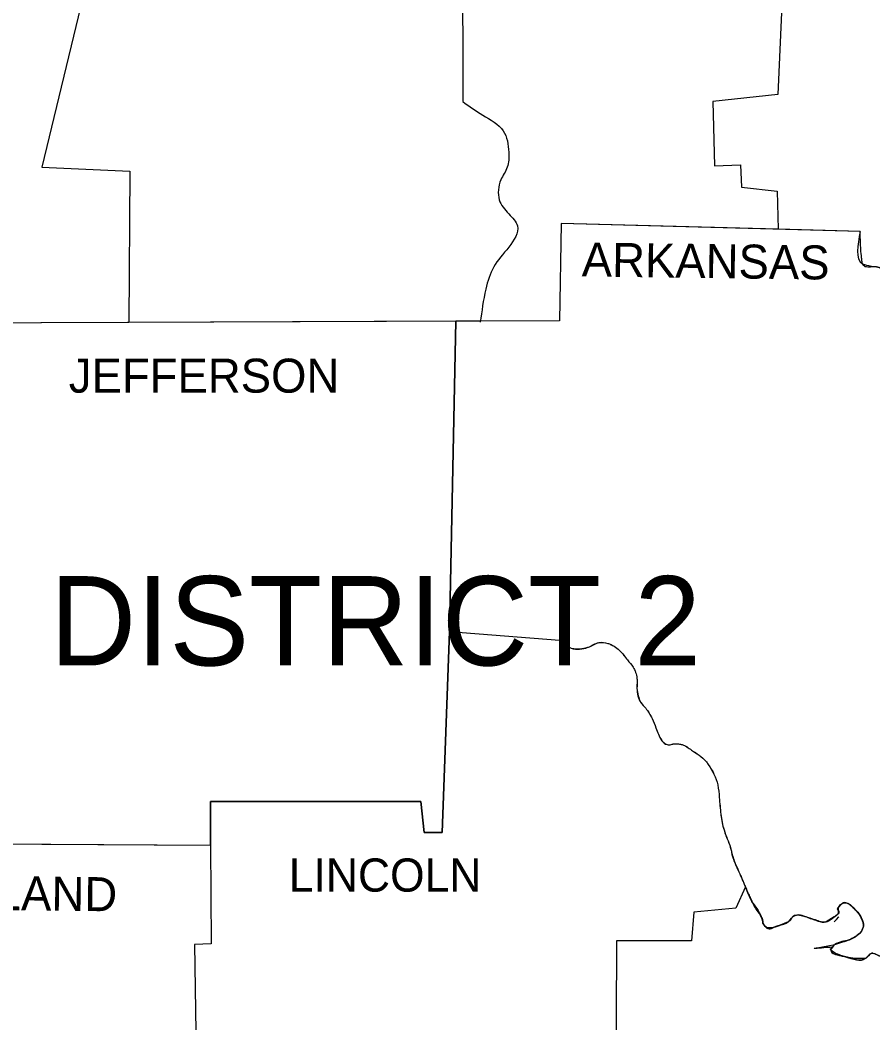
# Model space of a CAD drawing. Extents: x 3046 to 131673, y -8885 to 10756.
# Drawn here: x 28781 to 29835, y 6426 to 7667 of the extents above; entities that cross this region are included whole.
import ezdxf

# ---------------------------------------------------------------- set-up
doc = ezdxf.new("R2010")
doc.units = 0
for name, color, linetype in [('1', 7, 'Continuous'), ('2', 7, 'Continuous'), ('3', 7, 'Continuous'), ('R_Annotation', 7, 'Continuous')]:
    doc.layers.add(name, color=color, linetype=linetype)

msp = doc.modelspace()

# ---------------------------------------------------------------- linework, layer by layer
at = {"layer": '1'}
for points in [[(29187.61348452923, 8119.400186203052), (29189.570298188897, 7944.265365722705), (29327.52565951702, 7941.330145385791), (29328.50406627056, 7565.621927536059)], [(28801.142791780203, 8074.393472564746), (28857.890387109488, 8070.47984524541), (28858.868794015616, 7696.7284411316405), (28807.9916394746, 7484.414161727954), (28916.59479625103, 7479.52212750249), (28915.578457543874, 7292.515822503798)], [(29729.650861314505, 7842.511056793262), (29717.909979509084, 7574.427588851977), (29637.68062056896, 7565.621927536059), (29639.63743419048, 7486.370975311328), (29671.924859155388, 7487.349382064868), (29672.903266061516, 7459.953991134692), (29716.931572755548, 7455.06195713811), (29718.362445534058, 7407.843152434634)], [(29819.664288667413, 7405.163209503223), (29449.8265115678, 7414.947277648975), (29447.86969794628, 7294.603239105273), (28699.388482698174, 7291.668018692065)], [(29319.809376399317, 7294.101041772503), (29311.871150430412, 6910.089359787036), (29447.86969794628, 6899.326884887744)], [(29311.871150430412, 6910.089359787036), (29303.065488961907, 6661.574028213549), (29280.562132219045, 6661.574028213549), (29276.648504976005, 6699.731894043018), (29016.39229155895, 6699.731894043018), (29016.39229155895, 6644.941112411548)], [(28668.079464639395, 6647.876332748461), (29016.39229155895, 6645.919519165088)], [(29016.39229155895, 6645.919519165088), (29017.370698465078, 6523.618667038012), (28996.824155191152, 6522.640260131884), (29002.694596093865, 6116.601431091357)], [(29677.79530001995, 6594.063957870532), (29666.05441821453, 6567.646973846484), (29614.198856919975, 6562.754939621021), (29611.263636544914, 6527.532294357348), (29518.314988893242, 6527.532294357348), (29517.336581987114, 6234.988655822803)], [(29787.37686354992, 6551.014057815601), (29790.312084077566, 6553.949278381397), (29793.247304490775, 6556.88449871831), (29793.247304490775, 6556.88449871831)]]:
    msp.add_lwpolyline(points, dxfattribs=at)
for points in [[(29328.50406627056, 7565.621927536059), (29352.964236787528, 7548.98901158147), (29378.40281390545, 7529.420875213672), (29385.251661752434, 7503.003891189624), (29383.294848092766, 7484.414161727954), (29375.467593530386, 7468.759652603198), (29373.510779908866, 7444.299482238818), (29385.251661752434, 7426.688159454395), (29396.014136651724, 7412.0120571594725), (29385.251661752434, 7385.595073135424), (29366.66193210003, 7361.134902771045), (29356.877864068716, 7333.7395118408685), (29350.02901625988, 7292.646425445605)], [(29819.664288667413, 7405.163209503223), (29822.599509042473, 7365.048530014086), (29846.08127265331, 7359.178089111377), (29855.865340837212, 7348.415613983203), (29860.75737487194, 7325.912257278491), (29877.390290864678, 7316.128189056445), (29899.893647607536, 7302.430493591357), (29913.591343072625, 7292.646425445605), (29923.375411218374, 7276.99191632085), (29929.24585215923, 7251.5533390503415), (29944.90036124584, 7234.92042324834), (29966.425311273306, 7227.093168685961), (29982.079820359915, 7208.5034392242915), (29991.86388835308, 7182.086455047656), (30007.518397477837, 7170.345573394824), (30023.172906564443, 7149.799030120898), (30031.000161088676, 7140.9933688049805), (30044.697856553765, 7117.51160519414), (30058.39555201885, 7105.77072338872), (30068.1796202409, 7098.921875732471), (30083.834129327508, 7094.0298415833), (30103.402265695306, 7081.31055302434), (30116.121554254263, 7061.742416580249), (30116.121554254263, 7047.0663142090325), (30111.229520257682, 7024.562957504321), (30107.315892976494, 7001.081193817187), (30105.359079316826, 6974.664209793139), (30103.402265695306, 6951.1824461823), (30112.207927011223, 6931.614309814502), (30107.315892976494, 6902.262105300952), (30097.531824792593, 6886.607596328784), (30096.553417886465, 6865.082646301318), (30093.618197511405, 6832.7952212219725), (30089.704570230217, 6814.205491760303), (30080.898908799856, 6783.874880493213), (30068.1796202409, 6768.220371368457)], [(29447.86969794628, 6899.326884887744), (29462.545800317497, 6889.542816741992), (29483.092343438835, 6890.52122364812), (29496.790038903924, 6896.391664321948), (29507.552513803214, 6895.413257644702), (29522.22861617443, 6886.607596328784), (29532.012684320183, 6874.866714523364), (29538.861531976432, 6866.061053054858), (29543.75356616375, 6852.36335758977), (29543.75356616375, 6839.64406903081), (29548.645600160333, 6822.03274632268), (29554.51604106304, 6815.183898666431), (29562.34329562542, 6802.464609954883), (29567.23532977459, 6790.723728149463), (29570.17055014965, 6782.896473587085), (29580.933025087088, 6770.177185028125), (29590.717093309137, 6771.155591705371), (29599.522754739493, 6770.177185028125), (29611.263636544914, 6763.328337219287), (29628.87495929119, 6749.630641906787), (29631.810179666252, 6745.7170146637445), (29643.551061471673, 6720.278437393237), (29645.507875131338, 6704.623928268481), (29647.464688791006, 6684.077385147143), (29651.37831603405, 6664.509248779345), (29659.205570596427, 6642.984298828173), (29663.11919783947, 6628.308196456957), (29671.924859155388, 6607.7616533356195), (29677.79530001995, 6594.063957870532), (29685.622554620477, 6576.452635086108), (29697.363436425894, 6556.88449871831), (29702.25547061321, 6545.143617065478), (29718.888386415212, 6546.122023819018), (29730.629268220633, 6551.014057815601), (29739.43492953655, 6558.841312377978), (29750.19740462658, 6557.862905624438), (29761.938286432, 6553.949278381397), (29777.59279551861, 6551.014057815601), (29787.37686354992, 6556.88449871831), (29792.268897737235, 6560.798126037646), (29793.247304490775, 6569.603787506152), (29802.052965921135, 6574.4958215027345), (29811.837034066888, 6567.646973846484), (29822.599509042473, 6551.9924647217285), (29822.599509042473, 6542.208396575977), (29818.685881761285, 6536.337955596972), (29805.966593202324, 6528.5107011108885), (29788.355270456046, 6522.640260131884), (29783.463236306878, 6515.791412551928), (29800.096152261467, 6507.964157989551), (29826.513136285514, 6506.0073443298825), (29833.361984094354, 6511.877785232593), (29850.97330668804, 6506.985751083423), (29857.82215449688, 6511.877785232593), (29881.30391810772, 6510.899378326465), (29892.066393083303, 6518.726632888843), (29913.591343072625, 6517.748226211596), (29920.440190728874, 6512.856191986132), (29920.440190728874, 6504.050530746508), (29938.051513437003, 6500.136903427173), (29950.770802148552, 6503.07212384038), (29967.403717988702, 6498.180089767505), (29982.079820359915, 6490.352835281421), (29989.90707473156, 6479.590360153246), (29999.691142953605, 6467.849478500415), (30008.496804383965, 6470.7846988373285), (30015.345652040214, 6479.590360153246), (30030.02175441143, 6495.244869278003), (30030.02175441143, 6505.0289374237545), (30033.93538165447, 6511.877785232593), (30040.325643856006, 6524.658309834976)]]:
    msp.add_spline(points, degree=3, dxfattribs=at)
at = {"layer": 'R_Annotation'}
for p, q in [((29311.871150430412, 6910.089359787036), (29319.809376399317, 7294.101041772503)), ((29303.065488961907, 6661.574028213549), (29311.871150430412, 6910.089359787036)), ((29016.39229155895, 6645.919519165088), (29016.39229155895, 6699.731894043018)), ((29016.39229155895, 6699.731894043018), (29276.648504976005, 6699.731894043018)), ((28668.079464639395, 6647.876332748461), (29016.39229155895, 6645.919519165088)), ((29811.837034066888, 6567.646973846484), (29809.51763802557, 6569.843044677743)), ((29787.37686354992, 6556.88449871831), (29777.59279551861, 6551.0140578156)), ((29730.629268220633, 6551.014057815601), (29718.888386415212, 6546.122023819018)), ((29795.576998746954, 6525.2607142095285), (29805.966593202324, 6528.5107011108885)), ((29788.355270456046, 6522.640260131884), (29795.576998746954, 6525.2607142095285)), ((29800.096152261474, 6507.9641579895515), (29795.771773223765, 6509.362388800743)), ((29803.830930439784, 6506.963037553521), (29800.09615226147, 6507.964157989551)), ((29806.744939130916, 6506.371832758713), (29803.830930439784, 6506.963037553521)), ((29826.513136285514, 6506.007344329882), (29820.16929209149, 6505.464116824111)), ((29827.326065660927, 6506.25463626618), (29826.513136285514, 6506.0073443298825)), ((29828.38018533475, 6506.9892162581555), (29827.326065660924, 6506.254636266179)), ((29829.98095469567, 6508.828743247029), (29828.380185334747, 6506.989216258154)), ((29831.560026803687, 6510.725181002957), (29829.98095469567, 6508.828743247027)), ((29832.410036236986, 6511.439318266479), (29831.56002680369, 6510.72518100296)), ((29833.36198409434, 6511.8777852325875), (29832.41003623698, 6511.439318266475))]:
    msp.add_line(p, q, dxfattribs=at)
for points in [[(29819.664288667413, 7405.163209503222), (29718.362445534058, 7407.843152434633), (29449.8265115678, 7414.947277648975), (29447.86969794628, 7294.603239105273), (29350.24953628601, 7294.220414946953), (29319.809376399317, 7294.101041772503)], [(29319.809376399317, 7294.101041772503), (28915.578457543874, 7292.5158225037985), (28699.388482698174, 7291.668018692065)], [(29319.809376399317, 7294.101041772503), (29311.871150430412, 6910.089359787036), (29447.86969794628, 6899.326884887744)], [(29276.648504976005, 6699.731894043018), (29280.562132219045, 6661.574028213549), (29303.065488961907, 6661.574028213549)], [(29677.79530001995, 6594.063957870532), (29666.05441821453, 6567.646973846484), (29614.198856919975, 6562.754939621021), (29611.263636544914, 6527.532294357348), (29518.314988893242, 6527.532294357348), (29517.336581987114, 6234.988655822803)]]:
    msp.add_lwpolyline(points, dxfattribs=at)
for points in [[(30047.318353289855, 7114.88705362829), (30044.697856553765, 7117.51160519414), (30040.729209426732, 7123.013884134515), (30037.661243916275, 7129.140353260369), (30034.687160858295, 7135.322889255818), (30031.000161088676, 7140.9933688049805), (30023.172906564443, 7149.799030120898), (30019.17015857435, 7154.855787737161), (30015.31408279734, 7160.053666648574), (30011.473791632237, 7165.260863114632), (30007.518397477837, 7170.345573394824), (30003.913481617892, 7173.587226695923), (29999.673820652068, 7176.196124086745), (29995.44282081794, 7178.814966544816), (29991.86388835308, 7182.086455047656), (29988.57037909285, 7188.164055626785), (29986.640036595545, 7195.006916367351), (29984.875602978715, 7201.993792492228), (29982.079820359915, 7208.5034392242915), (29966.425311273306, 7227.093168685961), (29961.376789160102, 7229.7294498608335), (29955.768707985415, 7231.144447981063), (29950.10769094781, 7232.490620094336), (29944.90036124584, 7234.92042324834), (29940.264851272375, 7238.423466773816), (29936.032881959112, 7242.301376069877), (29929.24585215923, 7251.5533390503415), (29927.087361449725, 7257.764465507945), (29926.107285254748, 7264.272588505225), (29925.228882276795, 7270.780731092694), (29923.375411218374, 7276.99191632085), (29921.448171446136, 7281.231635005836), (29919.329897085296, 7285.385392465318), (29916.788362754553, 7289.256039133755), (29913.591343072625, 7292.646425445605), (29910.27664049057, 7295.344784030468), (29906.895281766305, 7297.844766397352), (29899.893647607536, 7302.430493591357), (29877.390290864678, 7316.128189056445), (29860.75737487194, 7325.912257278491), (29857.806507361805, 7330.218637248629), (29857.38127648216, 7336.212310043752), (29857.421086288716, 7342.681795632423), (29855.865340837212, 7348.415613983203), (29846.08127265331, 7359.178089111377), (29843.343667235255, 7360.539922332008), (29839.996088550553, 7361.08138538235), (29832.57803503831, 7360.985068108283), (29826.041159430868, 7361.4528715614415), (29823.79505312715, 7362.699485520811), (29822.599509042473, 7365.048530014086), (29821.753678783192, 7370.048372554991), (29821.11408341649, 7375.0534525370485), (29820.314800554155, 7385.077131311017), (29819.664288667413, 7405.163209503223)], [(29447.86969794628, 6899.326884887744), (29454.673477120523, 6893.419415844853), (29458.471108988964, 6891.195141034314), (29462.545800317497, 6889.542816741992), (29467.61169387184, 6888.582493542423), (29472.849786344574, 6888.6319425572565), (29483.092343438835, 6890.52122364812), (29486.54981741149, 6891.81741712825), (29489.93573272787, 6893.5745866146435), (29493.324377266, 6895.2726847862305), (29496.790038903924, 6896.391664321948), (29507.552513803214, 6895.413257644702), (29511.614254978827, 6893.756462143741), (29515.500180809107, 6891.839231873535), (29522.22861617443, 6886.607596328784), (29532.012684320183, 6874.866714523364), (29538.861531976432, 6866.061053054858), (29542.08707581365, 6859.500985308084), (29543.0563832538, 6855.9601700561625), (29543.75356616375, 6852.36335758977), (29543.974269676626, 6849.198836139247), (29543.81713237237, 6846.008732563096), (29543.6282119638, 6842.816119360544), (29543.75356616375, 6839.64406903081), (29545.279786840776, 6830.6414501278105), (29548.645600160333, 6822.03274632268), (29549.99633269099, 6820.163720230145), (29551.54674864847, 6818.520396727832), (29553.11420058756, 6816.92103610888), (29554.51604106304, 6815.183898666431), (29558.698739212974, 6808.985546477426), (29562.34329562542, 6802.464609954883), (29567.23532977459, 6790.723728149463), (29570.17055014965, 6782.896473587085), (29574.26728841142, 6775.370330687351), (29577.217547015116, 6772.310752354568), (29578.97194800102, 6771.106794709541), (29580.933025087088, 6770.177185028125), (29583.377548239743, 6769.83402784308), (29585.82441982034, 6770.2620866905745), (29588.271611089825, 6770.892296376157), (29590.717093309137, 6771.155591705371), (29595.122469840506, 6771.02505251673), (29599.522754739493, 6770.177185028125), (29611.263636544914, 6763.328337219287), (29628.87495929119, 6749.630641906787), (29631.810179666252, 6745.7170146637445), (29635.513190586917, 6739.597550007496), (29638.956128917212, 6733.40238631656), (29643.551061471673, 6720.278437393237), (29645.507875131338, 6704.623928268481), (29647.464688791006, 6684.077385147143), (29647.585287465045, 6683.047457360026)], [(29783.46323630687, 6515.791412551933), (29783.027164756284, 6516.469863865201), (29783.06753836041, 6517.329291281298), (29784.223345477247, 6519.33063915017), (29788.355270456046, 6522.640260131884), (29788.355270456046, 6522.640260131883)], [(29795.576998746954, 6525.2607142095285), (29788.355270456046, 6522.640260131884), (29783.463236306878, 6515.791412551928), (29800.096152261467, 6507.964157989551), (29806.744939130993, 6506.371832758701), (29813.507939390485, 6505.562049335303), (29820.169292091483, 6505.464116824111), (29826.513136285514, 6506.0073443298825), (29828.380185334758, 6506.989216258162), (29829.980954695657, 6508.828743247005), (29831.560026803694, 6510.725181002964), (29833.361984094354, 6511.877785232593), (29835.445011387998, 6512.006587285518), (29837.629298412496, 6511.494921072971), (29842.16678249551, 6509.408088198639), (29846.704698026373, 6507.333095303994), (29850.97330668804, 6506.985751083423), (29852.73766256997, 6507.943807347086), (29854.38682501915, 6509.4470521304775), (29856.041440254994, 6510.942654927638), (29857.82215449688, 6511.877785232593), (29863.453174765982, 6512.166015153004), (29869.534266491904, 6511.250729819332), (29875.629743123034, 6510.404370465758), (29881.30391810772, 6510.899378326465), (29884.114834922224, 6512.475406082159), (29886.68515559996, 6514.854165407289), (29889.255476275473, 6517.212344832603), (29892.066393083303, 6518.726632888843), (29897.19883250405, 6519.690380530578), (29902.670737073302, 6519.8907878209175), (29913.591343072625, 6517.748226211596), (29920.440190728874, 6512.856191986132), (29920.885075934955, 6510.805368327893), (29920.120890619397, 6508.307598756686), (29919.516355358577, 6505.882710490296), (29920.440190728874, 6504.050530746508), (29922.638330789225, 6502.801081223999), (29924.839063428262, 6501.825442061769), (29929.24499287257, 6500.582400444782), (29938.051513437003, 6500.136903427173), (29941.231595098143, 6500.76946893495), (29944.411760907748, 6501.901163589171), (29947.59162515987, 6502.884533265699), (29950.770802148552, 6503.07212384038), (29967.403717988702, 6498.180089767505), (29982.079820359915, 6490.352835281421), (29989.90707473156, 6479.590360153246), (29999.691142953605, 6467.849478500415), (30008.496804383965, 6470.7846988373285), (30015.345652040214, 6479.590360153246), (30018.957919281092, 6483.484696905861), (30022.784470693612, 6487.249460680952), (30026.560638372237, 6491.098301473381), (30030.02175441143, 6495.244869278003), (30030.63407243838, 6497.490044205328), (30030.188521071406, 6500.056321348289), (30029.65958637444, 6502.662889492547), (30030.02175441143, 6505.0289374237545), (30033.93538165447, 6511.877785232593), (30040.00955671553, 6524.1009202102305)], [(29795.771773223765, 6509.362388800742), (29788.90002167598, 6512.158818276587), (29783.463236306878, 6515.791412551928), (29783.463236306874, 6515.791412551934)], [(29835.44501138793, 6512.0065872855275), (29833.361984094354, 6511.877785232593), (29833.361984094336, 6511.8777852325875)]]:
    msp.add_spline(points, degree=3, dxfattribs=at)
for points, degree in [([(29647.585287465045, 6683.047457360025), (29648.34814526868, 6676.784851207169), (29649.63966603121, 6670.600429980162), (29651.37831603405, 6664.509248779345), (29653.483152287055, 6657.135171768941), (29656.928116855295, 6650.2529786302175), (29659.205570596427, 6642.984298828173), (29660.71588654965, 6638.164001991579), (29661.124789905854, 6632.961815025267), (29663.11919783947, 6628.308196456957), (29666.054418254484, 6621.459348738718), (29668.98963873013, 6614.610501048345), (29671.924859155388, 6607.7616533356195), (29673.88167277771, 6603.195754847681), (29675.838486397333, 6598.629856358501), (29677.79530001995, 6594.063957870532), (29680.32588738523, 6588.1592539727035), (29682.95361187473, 6582.295866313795), (29685.622554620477, 6576.452635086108), (29688.78281482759, 6569.533741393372), (29693.598078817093, 6563.434275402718), (29697.363436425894, 6556.88449871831), (29699.46213529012, 6553.2338470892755), (29698.977034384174, 6548.3598870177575), (29702.25547061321, 6545.143617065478), (29706.550067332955, 6540.930455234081), (29713.66877246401, 6544.387275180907), (29718.888386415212, 6546.122023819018), (29722.872968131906, 6547.446307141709), (29726.88866987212, 6549.025742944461), (29730.629268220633, 6551.014057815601), (29734.094096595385, 6552.85578717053), (29735.7305682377, 6557.873078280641), (29739.43492953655, 6558.841312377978), (29742.832819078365, 6559.729441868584), (29746.759407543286, 6558.881093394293), (29750.19740462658, 6557.862905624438), (29754.13458739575, 6556.69688039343), (29757.986079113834, 6555.1209429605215), (29761.938286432, 6553.949278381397), (29767.024594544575, 6552.441400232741), (29772.579997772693, 6549.970961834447), (29777.59279551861, 6551.014057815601), (29781.183888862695, 6551.761316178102), (29784.16142161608, 6554.653446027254), (29787.37686354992, 6556.88449871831), (29789.142344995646, 6558.109488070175), (29790.7658793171, 6559.356204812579), (29792.268897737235, 6560.798126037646), (29794.394486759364, 6562.837310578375), (29790.836459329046, 6567.056543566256), (29793.247304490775, 6569.603787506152), (29795.98834415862, 6572.499907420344), (29799.25632032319, 6575.24702865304), (29802.052965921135, 6574.4958215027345), (29805.36868427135, 6573.6051861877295), (29808.66459111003, 6570.785357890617), (29811.837034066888, 6567.646973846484), (29816.883314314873, 6562.654869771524), (29820.134839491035, 6557.877745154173), (29822.599509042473, 6551.9924647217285), (29823.868878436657, 6548.961391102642), (29823.78643263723, 6545.270583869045), (29822.599509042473, 6542.208396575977), (29821.743606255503, 6540.000221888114), (29820.58483804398, 6537.971112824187), (29818.685881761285, 6536.337955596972), (29814.666203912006, 6532.880916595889), (29810.422241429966, 6530.724138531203), (29805.966593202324, 6528.5107011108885), (29802.687221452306, 6526.881603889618), (29799.1261629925, 6526.186184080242), (29795.576998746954, 6525.260714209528)], 3), ([(29678.558165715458, 6592.29184233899), (29678.302941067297, 6592.882147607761), (29678.048633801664, 6593.4728457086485), (29677.79530001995, 6594.063957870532)], 2), ([(29702.25547061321, 6545.143617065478), (29698.977034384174, 6548.3598870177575), (29699.46213529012, 6553.2338470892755), (29697.363436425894, 6556.88449871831), (29693.598078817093, 6563.434275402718), (29688.78281482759, 6569.533741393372), (29685.622554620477, 6576.452635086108), (29683.220796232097, 6581.710908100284), (29680.852416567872, 6586.985503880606), (29678.558165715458, 6592.29184233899)], 3), ([(29793.247304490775, 6569.603787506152), (29790.836459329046, 6567.056543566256), (29794.394486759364, 6562.837310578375), (29792.268897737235, 6560.798126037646), (29790.905859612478, 6559.49049495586), (29789.443708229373, 6558.34340162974), (29787.866459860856, 6557.227464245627)], 3), ([(29809.51763802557, 6569.843044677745), (29807.07095404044, 6572.035218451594), (29804.567657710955, 6573.820349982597), (29802.052965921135, 6574.4958215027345), (29799.25632032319, 6575.24702865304), (29795.98834415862, 6572.499907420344), (29793.247304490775, 6569.603787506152)], 3), ([(29822.599509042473, 6551.9924647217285), (29820.134839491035, 6557.877745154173), (29816.883314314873, 6562.654869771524), (29811.837034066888, 6567.646973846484)], 2), ([(29734.22221290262, 6554.364048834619), (29733.152516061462, 6553.045875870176), (29732.043111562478, 6551.765586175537), (29730.629268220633, 6551.014057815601)], 2), ([(29750.19740462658, 6557.862905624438), (29746.759407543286, 6558.881093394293), (29742.832819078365, 6559.729441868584), (29739.43492953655, 6558.841312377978), (29737.242154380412, 6558.268171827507), (29735.77396347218, 6556.276250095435), (29734.22221290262, 6554.364048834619)], 3), ([(29777.59279551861, 6551.014057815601), (29772.579997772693, 6549.970961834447), (29767.024594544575, 6552.441400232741), (29761.938286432, 6553.949278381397), (29757.986079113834, 6555.1209429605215), (29754.13458739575, 6556.69688039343), (29750.19740462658, 6557.862905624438)], 3), ([(29787.866459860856, 6557.227464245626), (29787.70448075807, 6557.112860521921), (29787.54128775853, 6556.998585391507), (29787.37686354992, 6556.88449871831)], 2), ([(29818.685881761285, 6536.337955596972), (29820.58483804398, 6537.971112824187), (29821.743606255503, 6540.000221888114), (29822.599509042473, 6542.208396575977), (29823.78643263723, 6545.270583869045), (29823.868878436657, 6548.961391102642), (29822.599509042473, 6551.9924647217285)], 3), ([(29718.888386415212, 6546.122023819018), (29713.66877246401, 6544.387275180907), (29706.550067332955, 6540.930455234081), (29702.25547061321, 6545.143617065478)], 2), ([(29805.966593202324, 6528.5107011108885), (29810.422241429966, 6530.724138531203), (29814.666203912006, 6532.880916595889), (29818.685881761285, 6536.337955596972)], 2), ([(29820.169292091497, 6505.464116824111), (29815.81024190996, 6505.307830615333), (29811.239519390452, 6505.578984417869), (29806.744939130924, 6506.371832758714)], 2)]:
    msp.add_open_spline(points, degree=degree, dxfattribs=at)

# ---------------------------------------------------------------- texts
at = {"layer": '2'}
for s, height, rotation, p in [('ARKANSAS', 42.061709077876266, 359.2678250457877, (29475.26508883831, 7349.394020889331)), ('CLEVELAND', 42.07344995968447, 359.33765002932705, (28566.325155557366, 6567.646973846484))]:
    msp.add_text(s, height=height, rotation=rotation, dxfattribs=at).set_placement(p)
for s, height, p in [('JEFFERSON', 42.07344995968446, (28841.25747126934, 7205.568218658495)), ('LINCOLN', 41.09308632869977, (29113.25456652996, 6588.193516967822))]:
    msp.add_text(s, height=height, dxfattribs=at).set_placement(p)
at = {"layer": '3'}
msp.add_text('DISTRICT 2', height=110.55801354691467, dxfattribs=at).set_placement((28817.775707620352, 6868.0178667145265))

doc.saveas('drawing.dxf')
